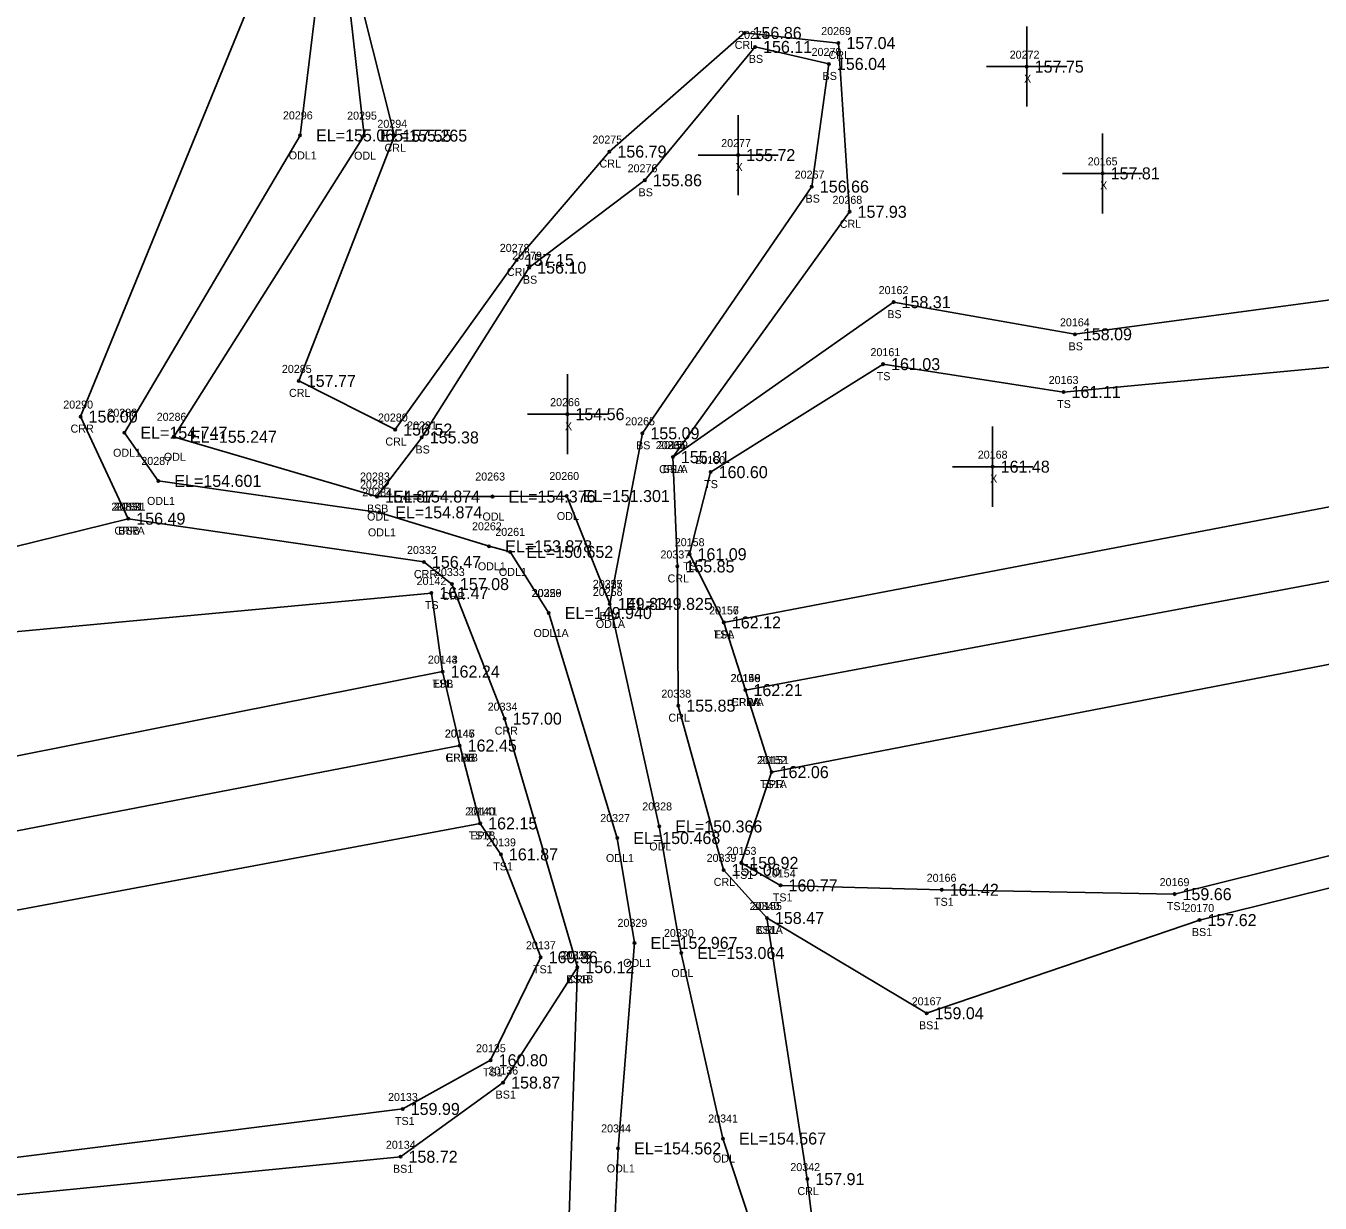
# Model space of a CAD drawing. Extents: x 2381545 to 2382928, y 1029933 to 1030589.
# Drawn here: x 2382147.9 to 2382309.6, y 1030313.9 to 1030461 of the extents above; entities that cross this region are included whole.
import ezdxf

# ---------------------------------------------------------------- set-up
doc = ezdxf.new("R2010")
doc.units = 0
for name, color, linetype in [('RD_DTM_BkLn1', 7, 'Continuous'), ('RD_DTM_BkLn2', 7, 'Continuous'), ('RD_DTM_BkLn_txCode', 7, 'Continuous'), ('RD_EX_H2O', 7, 'Continuous'), ('RD_EX_H2O_txCode', 7, 'Continuous'), ('RD_EX_Misc', 7, 'Continuous'), ('RD_EX_Misc_txCode', 7, 'Continuous'), ('RD_EX_Road', 7, 'Continuous'), ('RD_EX_Road_txCode', 7, 'Continuous'), ('RD_EX_TX_H2O_ELEV', 7, 'Continuous'), ('RD_EX_TX_Misc_ELEV', 7, 'Continuous'), ('RD_EX_TX_Road_ELEV', 7, 'Continuous'), ('RD_HC_Survey_ELEV', 7, 'Continuous'), ('RD_HC_Survey_txCode', 7, 'Continuous'), ('RD_SMD_Locator', 7, 'Continuous')]:
    doc.layers.add(name, color=color, linetype=linetype)

msp = doc.modelspace()

# ---------------------------------------------------------------- linework, layer by layer
at = {"layer": 'RD_DTM_BkLn1'}
for points in [[(2382237.83, 1030377.97), (2382343.9, 1030397.77), (2382436.97, 1030414.87), (2382557.72, 1030437.27), (2382666.29, 1030458.08), (2382780.92, 1030480.13), (2382908.6, 1030503.95)], [(2381547.18, 1030259.1), (2381595.71, 1030262.71), (2381646.12, 1030268.56), (2381695.78, 1030276.09), (2381799.52, 1030294.49), (2381897.44, 1030312.39), (2382008.24, 1030333.66), (2382118.08, 1030354.86), (2382202.13, 1030371.04)]]:
    msp.add_lwpolyline(points, dxfattribs=at)
at = {"layer": 'RD_DTM_BkLn2'}
for points in [[(2382220.88, 1030388.74), (2382224.95, 1030410.06), (2382246.12, 1030440.89), (2382248.25, 1030456.22), (2382239.03, 1030458.35), (2382225.26, 1030441.68), (2382210.81, 1030430.76), (2382197.39, 1030409.54), (2382191.8, 1030402.16)], [(2382228.76, 1030407.08), (2382256.33, 1030426.45), (2382278.98, 1030422.43), (2382339.75, 1030430.63), (2382431.47, 1030443.9), (2382462.65, 1030443.42), (2382466.62, 1030439.12)], [(2382235.13, 1030386.42), (2382230.84, 1030394.95), (2382233.48, 1030405.21), (2382255.02, 1030418.7), (2382277.57, 1030415.22), (2382339.26, 1030420.97), (2382433.29, 1030438.78), (2382461.79, 1030441.66), (2382466.62, 1030439.12)], [(2381793.09, 1030313.94), (2381875.92, 1030331.56), (2381878.21, 1030338.59), (2381904.22, 1030343.93), (2381908.67, 1030338.54), (2382000.53, 1030356.42), (2382114.53, 1030387.99), (2382160.73, 1030399.39)], [(2382241.1, 1030367.72), (2382237.31, 1030356.38), (2382242.21, 1030353.56), (2382262.35, 1030353.01), (2382291.43, 1030352.47), (2382349.66, 1030366.91), (2382440.08, 1030397.96)], [(2381904.22, 1030343.93), (2381906.64, 1030333.65), (2382003.16, 1030353.83), (2382114.61, 1030382.31), (2382198.59, 1030390.09), (2382200, 1030380.28)], [(2382240.51, 1030349.49), (2382260.46, 1030337.58), (2382294.55, 1030349.23), (2382350.1, 1030362.95), (2382424.24, 1030390.04)], [(2381785.89, 1030275.89), (2381871.01, 1030288.93), (2381880.52, 1030282.55), (2381901.68, 1030286.01), (2382013.28, 1030298.25), (2382122.09, 1030316.46), (2382195.01, 1030325.62), (2382206, 1030331.71), (2382212.25, 1030344.58), (2382207.28, 1030357.44), (2382204.69, 1030361.31)], [(2381786.8, 1030272.08), (2381870.97, 1030285.18), (2381880.6, 1030281.02), (2381901.08, 1030282.53), (2382011.65, 1030292.89), (2382122.26, 1030312.46), (2382194.74, 1030319.65), (2382207.56, 1030328.92), (2382216.83, 1030343.34)]]:
    msp.add_lwpolyline(points, dxfattribs=at)
at = {"layer": 'RD_EX_H2O'}
for points in [[(2382160.73, 1030399.39), (2382154.77, 1030412.15), (2382181.24, 1030476.87), (2382199.49, 1030496.35), (2382230.29, 1030508.71), (2382264.32, 1030549.47), (2382297.86, 1030572.8)], [(2382213.26, 1030387.6), (2382208.44, 1030395.24), (2382205.81, 1030395.94), (2382192.08, 1030400.18), (2382164.48, 1030404.11), (2382160.24, 1030410.13), (2382182.19, 1030447.29), (2382184.85, 1030469.16), (2382203.14, 1030494.91), (2382232.76, 1030506.19), (2382265.5, 1030548.12), (2382299.1, 1030569.06)], [(2382220.88, 1030388.74), (2382215.51, 1030402.22), (2382206.23, 1030402.16), (2382191.8, 1030402.16), (2382166.42, 1030409.62), (2382190.19, 1030447.26), (2382188.16, 1030465.42), (2382207.82, 1030492.06), (2382239.53, 1030497.2), (2382270.4, 1030543.81), (2382304.88, 1030567.67)], [(2382228.76, 1030407.08), (2382250.84, 1030437.74), (2382249.44, 1030458.83), (2382237.72, 1030460.09), (2382220.83, 1030445.27), (2382209.26, 1030431.73), (2382194.07, 1030410.53), (2382182.03, 1030416.61), (2382193.97, 1030447.24), (2382189.92, 1030463.42), (2382214.36, 1030489.72), (2382240.6, 1030493.89), (2382272.04, 1030542.69), (2382306.96, 1030567.72)], [(2382228.76, 1030407.08), (2382229.33, 1030393.42), (2382229.44, 1030376.02), (2382235.1, 1030355.5), (2382240.51, 1030349.49), (2382245.56, 1030316.86), (2382248.97, 1030289.05), (2382238.04, 1030280.56), (2382242.49, 1030255.05), (2382259.38, 1030214.05), (2382335.14, 1030213.97), (2382351.43, 1030124.97), (2382330.65, 1030084.53), (2382333.22, 1030050.31), (2382344.99, 1030019.27), (2382333.68, 1029961.92)], [(2382160.73, 1030399.39), (2382197.66, 1030393.98), (2382201.16, 1030391.22), (2382207.75, 1030374.4), (2382216.83, 1030343.34), (2382214.66, 1030277.58), (2382224.95, 1030248.16), (2382253.35, 1030190.66), (2382280.97, 1030189.84), (2382308.61, 1030179.94), (2382336.27, 1030122.7), (2382320.51, 1030086.69), (2382321.43, 1030050.4), (2382332.53, 1030017.35), (2382333.68, 1029961.92)], [(2382213.26, 1030387.6), (2382221.81, 1030359.48), (2382223.97, 1030346.38), (2382221.92, 1030320.69), (2382220.3, 1030284.96), (2382227.77, 1030249.4), (2382256.92, 1030199.53), (2382280.94, 1030192.97), (2382312.22, 1030183.5), (2382338.65, 1030122.69), (2382323.29, 1030086.32), (2382328.28, 1030050.33), (2382335.32, 1030017.57), (2382333.68, 1029961.92)], [(2382220.88, 1030388.74), (2382227.06, 1030360.93), (2382229.81, 1030345.11), (2382235.02, 1030321.93), (2382245.69, 1030289.44), (2382231.02, 1030286.27), (2382239.27, 1030255.62), (2382259.54, 1030209.53), (2382328.62, 1030208.08), (2382346.92, 1030124.75), (2382326.86, 1030085.52), (2382331.57, 1030050.13), (2382343.53, 1030018.97), (2382333.68, 1029961.92)]]:
    msp.add_lwpolyline(points, dxfattribs=at)
at = {"layer": 'RD_EX_Misc'}
for p, q in [((2382272.96, 1030450.88), (2382272.96, 1030460.88)), ((2382267.96, 1030455.88), (2382277.96, 1030455.88)), ((2382236.92, 1030439.83), (2382236.92, 1030449.83)), ((2382282.45, 1030437.54), (2382282.45, 1030447.54)), ((2382231.92, 1030444.83), (2382241.92, 1030444.83)), ((2382277.45, 1030442.54), (2382287.45, 1030442.54)), ((2382215.59, 1030407.45), (2382215.59, 1030417.45)), ((2382210.59, 1030412.45), (2382220.59, 1030412.45)), ((2382268.71, 1030400.89), (2382268.71, 1030410.89)), ((2382263.71, 1030405.89), (2382273.71, 1030405.89))]:
    msp.add_line(p, q, dxfattribs=at)
at = {"layer": 'RD_EX_Road'}
for points in [[(2382237.83, 1030377.97), (2382235.13, 1030386.42), (2382342.38, 1030406.92), (2382435.08, 1030424.16), (2382555.51, 1030447.01), (2382663.83, 1030467.83), (2382778.84, 1030489.45), (2382906.57, 1030513.81)], [(2382237.83, 1030377.97), (2382241.1, 1030367.72), (2382346.41, 1030388.08), (2382437.98, 1030404.17), (2382559.51, 1030427.48), (2382667.4, 1030448.54), (2382782.14, 1030469.8), (2382910.48, 1030494.44)], [(2381547.21, 1030268.01), (2381595.28, 1030271.86), (2381645.28, 1030277.12), (2381675.41, 1030281.84), (2381694.68, 1030285.03), (2381797.68, 1030303.35), (2381895.95, 1030322.08), (2382005.53, 1030342.57), (2382116.42, 1030363.72), (2382200, 1030380.28), (2382202.13, 1030371.04)], [(2381547.49, 1030248.39), (2381596.55, 1030252.33), (2381646.64, 1030258.33), (2381698.19, 1030266.34), (2381800.73, 1030284.35), (2381899.22, 1030302.47), (2382010.02, 1030323.79), (2382119.81, 1030345.41), (2382204.69, 1030361.31), (2382202.13, 1030371.04)]]:
    msp.add_lwpolyline(points, dxfattribs=at)
at = {"layer": 'RD_SMD_Locator'}
for centre in [(2382237.72, 1030460.09), (2382249.44, 1030458.83), (2382239.03, 1030458.35), (2382248.25, 1030456.22), (2382272.96, 1030455.88), (2382182.19, 1030447.29), (2382190.19, 1030447.26), (2382193.97, 1030447.24), (2382220.83, 1030445.27), (2382236.92, 1030444.83), (2382282.45, 1030442.54), (2382225.26, 1030441.68), (2382246.12, 1030440.89), (2382250.84, 1030437.74), (2382209.26, 1030431.73), (2382210.81, 1030430.76), (2382256.33, 1030426.45), (2382278.98, 1030422.43), (2382255.02, 1030418.7), (2382182.03, 1030416.61), (2382277.57, 1030415.22), (2382154.77, 1030412.15), (2382215.59, 1030412.45), (2382160.24, 1030410.13), (2382194.07, 1030410.53), (2382224.95, 1030410.06), (2382166.42, 1030409.62), (2382197.39, 1030409.54), (2382228.76, 1030407.08), (2382228.76, 1030407.08), (2382228.76, 1030407.08), (2382233.48, 1030405.21), (2382268.71, 1030405.89), (2382164.48, 1030404.11), (2382191.8, 1030402.16), (2382191.8, 1030402.16), (2382206.23, 1030402.16), (2382215.51, 1030402.22), (2382160.73, 1030399.39), (2382160.73, 1030399.39), (2382160.73, 1030399.39), (2382192.08, 1030400.18), (2382205.81, 1030395.94), (2382197.66, 1030393.98), (2382208.44, 1030395.24), (2382230.84, 1030394.95), (2382229.33, 1030393.42), (2382201.16, 1030391.22), (2382198.59, 1030390.09), (2382213.26, 1030387.6), (2382213.26, 1030387.6), (2382220.88, 1030388.74), (2382220.88, 1030388.74), (2382220.88, 1030388.74), (2382235.13, 1030386.42), (2382235.13, 1030386.42), (2382200, 1030380.28), (2382200, 1030380.28), (2382237.83, 1030377.97), (2382237.83, 1030377.97), (2382237.83, 1030377.97), (2382229.44, 1030376.02), (2382207.75, 1030374.4), (2382202.13, 1030371.04), (2382202.13, 1030371.04), (2382202.13, 1030371.04), (2382241.1, 1030367.72), (2382241.1, 1030367.72), (2382204.69, 1030361.31), (2382204.69, 1030361.31), (2382227.06, 1030360.93), (2382221.81, 1030359.48), (2382207.28, 1030357.44), (2382235.1, 1030355.5), (2382237.31, 1030356.38), (2382242.21, 1030353.56), (2382262.35, 1030353.01), (2382291.43, 1030352.47), (2382240.51, 1030349.49), (2382240.51, 1030349.49), (2382294.55, 1030349.23), (2382223.97, 1030346.38), (2382212.25, 1030344.58), (2382229.81, 1030345.11), (2382216.83, 1030343.34), (2382216.83, 1030343.34), (2382260.46, 1030337.58), (2382206, 1030331.71), (2382207.56, 1030328.92), (2382195.01, 1030325.62), (2382235.02, 1030321.93), (2382194.74, 1030319.65), (2382221.92, 1030320.69), (2382245.56, 1030316.86)]:
    msp.add_circle(centre, 0.15, dxfattribs=at)

# ---------------------------------------------------------------- texts
at = {"layer": 'RD_DTM_BkLn_txCode'}
for s, p in [('20274', (2382236.91, 1030459.35)), ('BS', (2382238.25, 1030456.35)), ('20270', (2382246.09, 1030457.22)), ('BS', (2382247.47, 1030454.22)), ('20276', (2382223.11, 1030442.68)), ('20267', (2382243.98, 1030441.89)), ('BS', (2382224.48, 1030439.68)), ('BS', (2382245.34, 1030438.89)), ('20279', (2382208.69, 1030431.76)), ('BS', (2382210.03, 1030428.76)), ('20162', (2382254.47, 1030427.45)), ('BS', (2382255.55, 1030424.45)), ('20164', (2382277.12, 1030423.43)), ('BS', (2382278.2, 1030420.43)), ('20161', (2382253.45, 1030419.7)), ('TS', (2382254.23, 1030416.7)), ('20163', (2382275.71, 1030416.22)), ('TS', (2382276.77, 1030413.22)), ('20265', (2382222.81, 1030411.06)), ('20281', (2382195.56, 1030410.54)), ('BS', (2382196.61, 1030407.54)), ('BS', (2382224.17, 1030408.06)), ('20159', (2382226.92, 1030408.08)), ('20160', (2382231.58, 1030406.21)), ('BSA', (2382227.49, 1030405.08)), ('20282', (2382189.68, 1030403.16)), ('TS', (2382232.68, 1030403.21)), ('20131', (2382159.18, 1030400.39)), ('BSB', (2382190.55, 1030400.16)), ('BSB', (2382159.48, 1030397.39)), ('20158', (2382229, 1030395.95)), ('TS', (2382230.04, 1030392.95)), ('20142', (2382196.75, 1030391.09)), ('20258', (2382218.76, 1030389.74)), ('TS', (2382197.79, 1030388.09)), ('BSA', (2382219.61, 1030386.74)), ('20157', (2382233.3, 1030387.42)), ('TSA', (2382233.85, 1030384.42)), ('20143', (2382198.16, 1030381.28)), ('TSB', (2382198.73, 1030378.28)), ('20152', (2382239.26, 1030368.72)), ('TS1A', (2382239.65, 1030365.72)), ('20140', (2382202.81, 1030362.31)), ('TS1B', (2382203.26, 1030359.31)), ('20139', (2382205.44, 1030358.44)), ('20153', (2382235.48, 1030357.38)), ('TS1', (2382206.32, 1030355.44)), ('TS1', (2382236.35, 1030354.38)), ('20154', (2382240.38, 1030354.56)), ('20166', (2382260.47, 1030354.01)), ('20169', (2382289.57, 1030353.47)), ('TS1', (2382241.25, 1030351.56)), ('TS1', (2382261.39, 1030351.01)), ('20155', (2382238.67, 1030350.49)), ('TS1', (2382290.47, 1030350.47)), ('20170', (2382292.67, 1030350.23)), ('BS1A', (2382239.07, 1030347.49)), ('BS1', (2382293.6, 1030347.23)), ('20137', (2382210.41, 1030345.58)), ('20138', (2382214.99, 1030344.34)), ('TS1', (2382211.29, 1030342.58)), ('BS1B', (2382215.41, 1030341.34)), ('20167', (2382258.6, 1030338.58)), ('BS1', (2382259.51, 1030335.58)), ('20135', (2382204.17, 1030332.71)), ('20136', (2382205.71, 1030329.92)), ('TS1', (2382205.04, 1030329.71)), ('20133', (2382193.18, 1030326.62)), ('BS1', (2382206.62, 1030326.92)), ('TS1', (2382194.05, 1030323.62)), ('20134', (2382192.91, 1030320.65)), ('BS1', (2382193.8, 1030317.65))]:
    msp.add_text(s, height=1, dxfattribs=at).set_placement(p)
at = {"layer": 'RD_EX_H2O_txCode'}
for s, p in [('20269', (2382247.29, 1030459.83)), ('CRL', (2382236.49, 1030458.09)), ('CRL', (2382248.21, 1030456.83)), ('20296', (2382180.05, 1030449.29)), ('20295', (2382188.07, 1030449.26)), ('20294', (2382191.85, 1030448.24)), ('20275', (2382218.71, 1030446.27)), ('CRL', (2382192.74, 1030445.24)), ('ODL1', (2382180.78, 1030444.29)), ('ODL', (2382188.94, 1030444.26)), ('CRL', (2382219.6, 1030443.27)), ('20268', (2382248.7, 1030438.74)), ('CRL', (2382249.61, 1030435.74)), ('20278', (2382207.14, 1030432.73)), ('CRL', (2382208.03, 1030429.73)), ('20285', (2382179.92, 1030417.61)), ('CRL', (2382180.81, 1030414.61)), ('20290', (2382152.61, 1030413.15)), ('20288', (2382158.12, 1030412.13)), ('20286', (2382164.28, 1030411.62)), ('20280', (2382191.92, 1030411.53)), ('CRR', (2382153.52, 1030410.15)), ('CRL', (2382192.85, 1030408.53)), ('20264', (2382226.62, 1030408.08)), ('20336', (2382226.62, 1030408.08)), ('ODL1', (2382158.83, 1030407.13)), ('20287', (2382162.36, 1030406.11)), ('ODL', (2382165.18, 1030406.62)), ('20260', (2382213.33, 1030404.22)), ('CRLA', (2382227.04, 1030405.08)), ('CRLA', (2382227.04, 1030405.08)), ('20283', (2382189.68, 1030404.16)), ('20263', (2382204.08, 1030404.16)), ('ODL1', (2382163.07, 1030401.11)), ('20284', (2382189.96, 1030402.18)), ('20289', (2382158.61, 1030400.39)), ('20331', (2382158.9, 1030400.39)), ('ODL', (2382190.56, 1030399.16)), ('20262', (2382203.67, 1030397.94)), ('ODL', (2382204.98, 1030399.16)), ('ODL', (2382214.27, 1030399.22)), ('CRRA', (2382158.99, 1030397.39)), ('CRRA', (2382158.99, 1030397.39)), ('ODL1', (2382190.67, 1030397.18)), ('20261', (2382206.58, 1030397.24)), ('20332', (2382195.55, 1030394.98)), ('ODL1', (2382204.4, 1030392.94)), ('20337', (2382227.21, 1030394.42)), ('CRR', (2382196.41, 1030391.98)), ('20333', (2382199.04, 1030392.22)), ('ODL1', (2382207.03, 1030392.24)), ('CRL', (2382228.1, 1030391.42)), ('20257', (2382218.76, 1030390.74)), ('20325', (2382218.76, 1030390.74)), ('CRR', (2382199.91, 1030389.22)), ('20326', (2382211.11, 1030389.6)), ('20259', (2382211.14, 1030389.6)), ('ODLA', (2382219.14, 1030385.74)), ('ODLA', (2382219.14, 1030385.74)), ('ODL1A', (2382211.36, 1030384.6)), ('ODL1A', (2382211.36, 1030384.6)), ('20338', (2382227.32, 1030377.02)), ('20334', (2382205.63, 1030375.4)), ('CRL', (2382228.21, 1030374.02)), ('CRR', (2382206.5, 1030372.4)), ('20328', (2382224.94, 1030362.93)), ('20327', (2382219.69, 1030361.48)), ('ODL', (2382225.82, 1030357.93)), ('ODL1', (2382220.4, 1030356.48)), ('20339', (2382232.98, 1030356.5)), ('CRL', (2382233.87, 1030353.5)), ('20340', (2382238.35, 1030350.49)), ('20329', (2382221.85, 1030348.38)), ('20330', (2382227.65, 1030347.11)), ('CRL', (2382239.28, 1030347.49)), ('20335', (2382214.71, 1030344.34)), ('ODL1', (2382222.56, 1030343.38)), ('CRR', (2382215.57, 1030341.34)), ('ODL', (2382228.57, 1030342.11)), ('20341', (2382233.18, 1030323.93)), ('20344', (2382219.8, 1030322.69)), ('ODL', (2382233.77, 1030318.93)), ('ODL1', (2382220.51, 1030317.69)), ('20342', (2382243.44, 1030317.86)), ('CRL', (2382244.33, 1030314.86))]:
    msp.add_text(s, height=1, dxfattribs=at).set_placement(p)
at = {"layer": 'RD_EX_Misc_txCode'}
for s, p in [('20272', (2382270.84, 1030456.88)), ('X', (2382272.64, 1030453.88)), ('20277', (2382234.8, 1030445.83)), ('20165', (2382280.59, 1030443.54)), ('X', (2382236.6, 1030442.83)), ('X', (2382282.14, 1030440.54)), ('20266', (2382213.43, 1030413.45)), ('X', (2382215.28, 1030410.45)), ('20168', (2382266.85, 1030406.89)), ('X', (2382268.4, 1030403.89))]:
    msp.add_text(s, height=1, dxfattribs=at).set_placement(p)
at = {"layer": 'RD_EX_Road_txCode'}
for s, p in [('20156', (2382233.28, 1030387.42)), ('EPL', (2382233.93, 1030384.42)), ('20144', (2382198.16, 1030381.28)), ('20150', (2382235.96, 1030378.97)), ('20149', (2382236, 1030378.97)), ('EPL', (2382198.79, 1030378.28)), ('EPRA', (2382236.12, 1030375.97)), ('EPLA', (2382236.14, 1030375.97)), ('20146', (2382200.27, 1030372.04)), ('20145', (2382200.3, 1030372.04)), ('EPRB', (2382200.43, 1030369.04)), ('EPLB', (2382200.45, 1030369.04)), ('20151', (2382239.54, 1030368.72)), ('EPR', (2382239.87, 1030365.72)), ('20141', (2382203.14, 1030362.31)), ('EPR', (2382203.46, 1030359.31))]:
    msp.add_text(s, height=1, dxfattribs=at).set_placement(p)
at = {"layer": 'RD_EX_TX_H2O_ELEV'}
for s, p in [('156.86', (2382238.72, 1030459.34)), ('157.04', (2382250.44, 1030458.08)), ('EL=155.065', (2382184.19, 1030446.54)), ('EL=155.265', (2382192.19, 1030446.51)), ('157.55', (2382194.97, 1030446.49)), ('156.79', (2382221.83, 1030444.52)), ('157.93', (2382251.84, 1030436.99)), ('157.15', (2382210.26, 1030430.98)), ('157.77', (2382183.03, 1030415.86)), ('156.00', (2382155.77, 1030411.4)), ('EL=154.747', (2382162.24, 1030409.38)), ('EL=155.247', (2382168.42, 1030408.87)), ('156.52', (2382195.07, 1030409.78)), ('155.81', (2382229.76, 1030406.33)), ('155.81', (2382229.76, 1030406.33)), ('EL=154.601', (2382166.48, 1030403.36)), ('EL=154.874', (2382193.8, 1030401.41)), ('EL=154.376', (2382208.23, 1030401.41)), ('EL=151.301', (2382217.51, 1030401.47)), ('EL=154.874', (2382194.08, 1030399.43)), ('156.49', (2382161.73, 1030398.64)), ('156.49', (2382161.73, 1030398.64)), ('EL=153.878', (2382207.81, 1030395.19)), ('EL=150.652', (2382210.44, 1030394.49)), ('156.47', (2382198.66, 1030393.23)), ('155.85', (2382230.33, 1030392.67)), ('157.08', (2382202.16, 1030390.47)), ('EL=149.825', (2382222.88, 1030387.99)), ('EL=149.825', (2382222.88, 1030387.99)), ('EL=149.940', (2382215.26, 1030386.85)), ('EL=149.940', (2382215.26, 1030386.85)), ('155.85', (2382230.44, 1030375.27)), ('157.00', (2382208.75, 1030373.65)), ('EL=150.366', (2382229.06, 1030360.18)), ('EL=150.468', (2382223.81, 1030358.73)), ('155.06', (2382236.1, 1030354.75)), ('158.47', (2382241.51, 1030348.74)), ('EL=152.967', (2382225.97, 1030345.63)), ('EL=153.064', (2382231.81, 1030344.36)), ('156.12', (2382217.83, 1030342.59)), ('EL=154.562', (2382223.92, 1030319.94)), ('EL=154.567', (2382237.02, 1030321.18)), ('157.91', (2382246.56, 1030316.11))]:
    msp.add_text(s, height=1.5, dxfattribs=at).set_placement(p)
at = {"layer": 'RD_EX_TX_Misc_ELEV'}
for s, p in [('156.11', (2382240.03, 1030457.6)), ('156.04', (2382249.25, 1030455.47)), ('157.75', (2382273.96, 1030455.13)), ('155.72', (2382237.92, 1030444.08)), ('155.86', (2382226.26, 1030440.93)), ('157.81', (2382283.45, 1030441.79)), ('156.66', (2382247.12, 1030440.14)), ('156.10', (2382211.81, 1030430.01)), ('158.31', (2382257.33, 1030425.7)), ('158.09', (2382279.98, 1030421.68)), ('161.03', (2382256.02, 1030417.95)), ('161.11', (2382278.57, 1030414.47)), ('154.56', (2382216.59, 1030411.7)), ('155.38', (2382198.39, 1030408.79)), ('155.09', (2382225.95, 1030409.31)), ('155.81', (2382229.76, 1030406.33)), ('160.60', (2382234.48, 1030404.46)), ('161.48', (2382269.71, 1030405.14)), ('154.87', (2382192.8, 1030401.41)), ('156.49', (2382161.73, 1030398.64)), ('161.09', (2382231.84, 1030394.2)), ('161.47', (2382199.59, 1030389.34)), ('149.83', (2382221.88, 1030387.99)), ('162.12', (2382236.13, 1030385.67)), ('162.24', (2382201, 1030379.53)), ('162.06', (2382242.1, 1030366.97)), ('162.15', (2382205.69, 1030360.56)), ('161.87', (2382208.28, 1030356.69)), ('159.92', (2382238.31, 1030355.63)), ('160.77', (2382243.21, 1030352.81)), ('161.42', (2382263.35, 1030352.26)), ('159.66', (2382292.43, 1030351.72)), ('158.47', (2382241.51, 1030348.74)), ('157.62', (2382295.55, 1030348.48)), ('160.36', (2382213.25, 1030343.83)), ('156.12', (2382217.83, 1030342.59)), ('159.04', (2382261.46, 1030336.83)), ('160.80', (2382207, 1030330.96)), ('158.87', (2382208.56, 1030328.17)), ('159.99', (2382196.01, 1030324.87)), ('158.72', (2382195.74, 1030318.9))]:
    msp.add_text(s, height=1.5, dxfattribs=at).set_placement(p)
at = {"layer": 'RD_EX_TX_Road_ELEV'}
for s, p in [('162.12', (2382236.13, 1030385.67)), ('162.24', (2382201, 1030379.53)), ('162.21', (2382238.83, 1030377.22)), ('162.21', (2382238.83, 1030377.22)), ('162.45', (2382203.13, 1030370.29)), ('162.45', (2382203.13, 1030370.29)), ('162.06', (2382242.1, 1030366.97)), ('162.15', (2382205.69, 1030360.56))]:
    msp.add_text(s, height=1.5, dxfattribs=at).set_placement(p)
at = {"layer": 'RD_HC_Survey_ELEV'}
for s, p in [('162.21', (2382238.83, 1030377.22)), ('162.45', (2382203.13, 1030370.29))]:
    msp.add_text(s, height=1.5, dxfattribs=at).set_placement(p)
at = {"layer": 'RD_HC_Survey_txCode'}
for s, p in [('20148', (2382236, 1030378.97)), ('CRWA', (2382236.03, 1030375.97)), ('20147', (2382200.3, 1030372.04)), ('CRWB', (2382200.34, 1030369.04))]:
    msp.add_text(s, height=1, dxfattribs=at).set_placement(p)

doc.saveas('drawing.dxf')
